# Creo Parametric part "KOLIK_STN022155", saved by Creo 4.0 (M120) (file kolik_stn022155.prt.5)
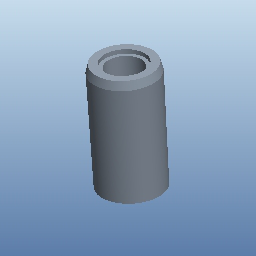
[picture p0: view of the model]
Units: Custom; MM, KILOGRAM, SECS
Materials in the file: OCEL

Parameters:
  PTC_MATERIAL_NAME = "OCEL"
  NAZOV = "KOLIK_STN022155"
  NORMA = "STN 02 2155"

Other parameters: HMOTNOST, HUSTOTA, D1

Created from: C022155.PRT

Other named items: BLIND

Layers: 1, 2, 3, 4, 5, 6, 7, 8, 9, 10, 11, 12, 13, 14, 15, 16, 17, 18, 19, 20, 21, 22, 23, 24, 25, 26, 27, 28, 29, 30, 31, 32

Family table entries: GENERIC, KOLIK_6, KOLIK_STN022155, value(d_val), 2/$, value(i_val), KOLIK_8, KOLIK_STN022155, !/ , 2/(, KOLIK_10, KOLIK_STN022155, !/$, 2/0, KOLIK_12, KOLIK_STN022155, !/(, 2/ , 2/4, 2/%, KOLIK_16, KOLIK_STN022155, !/0, 2/$, 2/%, 2/9, 2/-, KOLIK_20, KOLIK_STN022155, !/4, 2/(, 2/*, 2/<, KOLIK_25, KOLIK_STN022155, !/9, 2/0, 2/1, 2/6, KOLIK_30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

Surfaces: 6 cone, 6 cylinder, 4 plane, 2 torus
